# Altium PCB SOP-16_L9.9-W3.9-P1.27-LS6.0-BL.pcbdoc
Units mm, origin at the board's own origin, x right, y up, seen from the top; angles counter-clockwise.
Board outline 23.06 x 20.28 mm, 2 copper layers (Top Layer, Bottom Layer), stack 0 mm thick; 1 components, 0 nets, 16 pads, 0 vias.
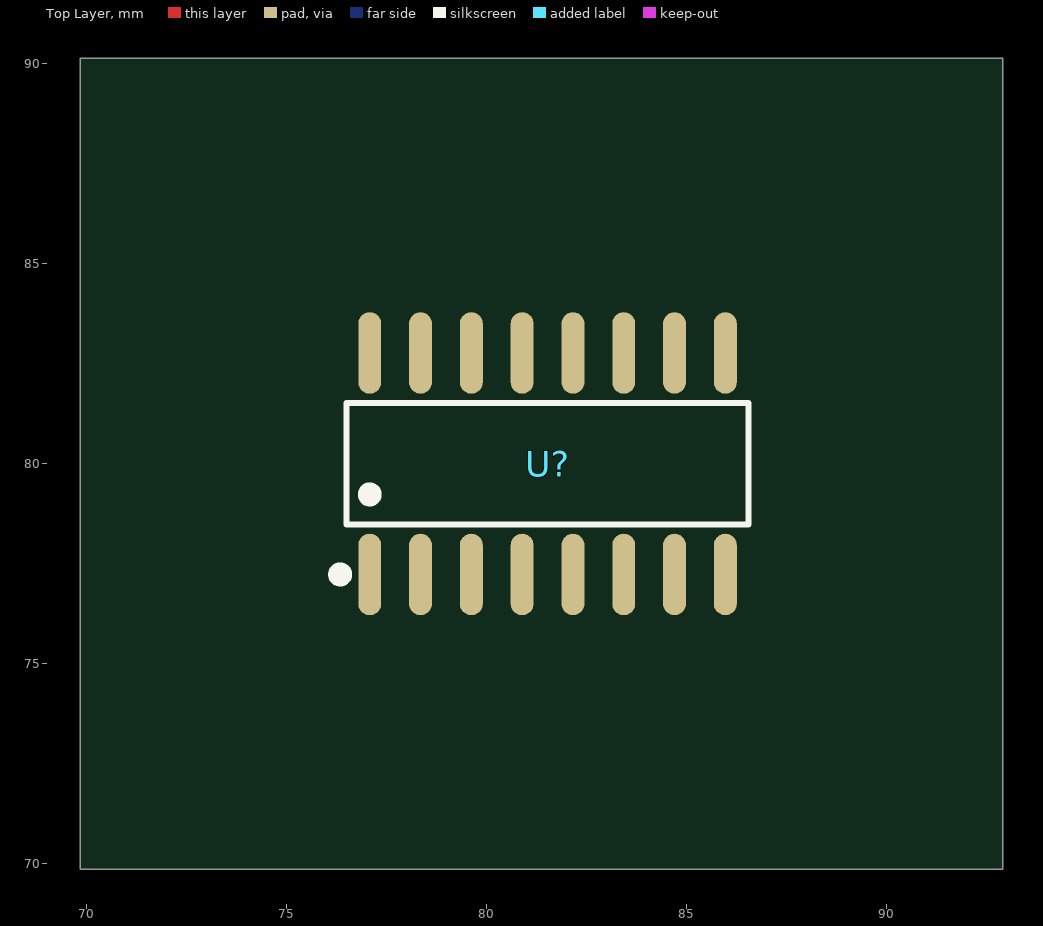
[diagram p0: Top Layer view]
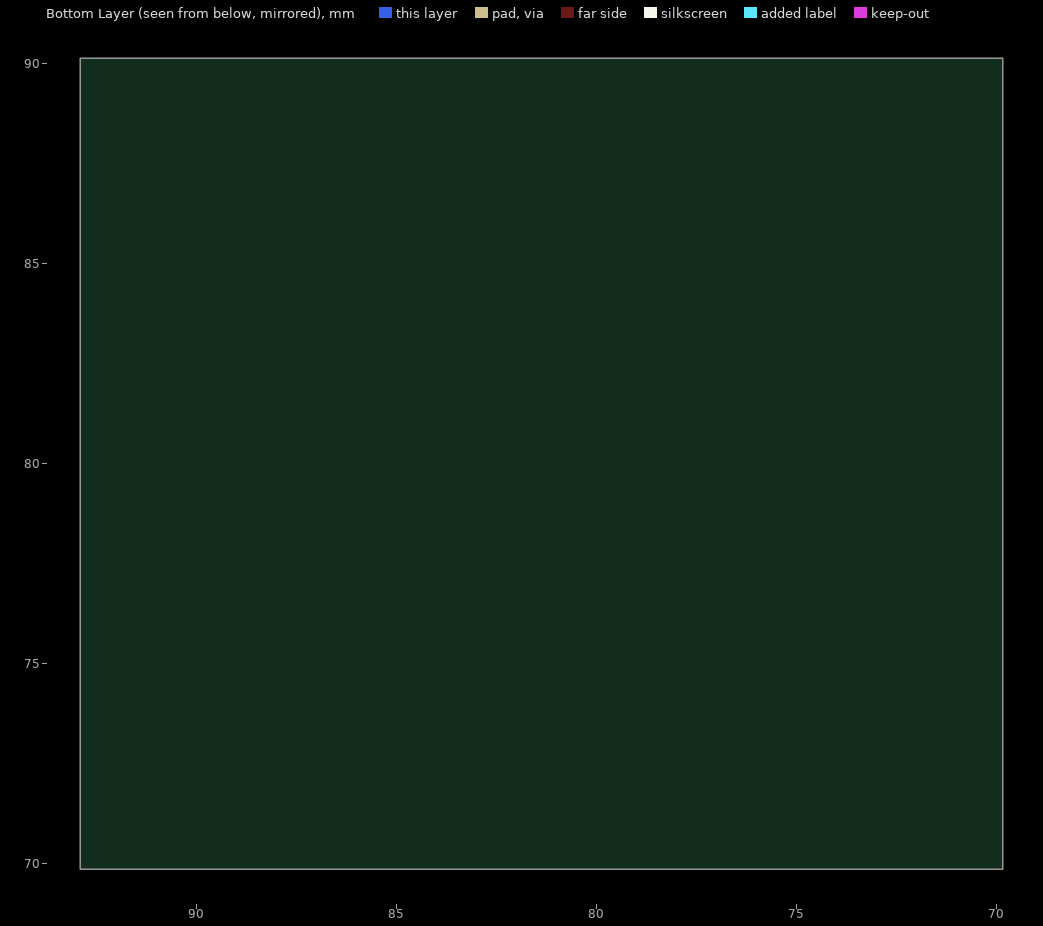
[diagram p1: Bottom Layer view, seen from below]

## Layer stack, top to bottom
Top Layer: signal copper (thickness not stored)
Bottom Layer: signal copper (thickness not stored)

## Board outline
92.911,69.85 69.85,69.85 69.85,90.126 92.911,90.126

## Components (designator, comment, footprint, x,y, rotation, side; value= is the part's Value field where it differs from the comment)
U? "" SOP-16_L9.9-W3.9-P1.27-LS6.0-BL 81.535,79.988 r0 top

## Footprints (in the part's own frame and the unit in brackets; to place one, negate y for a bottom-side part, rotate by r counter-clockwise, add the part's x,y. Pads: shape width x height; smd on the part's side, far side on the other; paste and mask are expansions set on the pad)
SOP-16_L9.9-W3.9-P1.27-LS6.0-BL [mm]
  oval 0.574x2.038 smd: 1(-4.445,-2.769) 2(-3.175,-2.769) 3(-1.905,-2.769) 4(-0.635,-2.769) 5(0.635,-2.769) 6(1.905,-2.769) 7(3.175,-2.769) 8(4.445,-2.769) 9(4.445,2.769) 10(3.175,2.769) 11(1.905,2.769) 12(0.635,2.769) 13(-0.635,2.769) 14(-1.905,2.769) 15(-3.175,2.769) 16(-4.445,2.769)
  silkscreen extent -5.33,-2.92 5.03,1.52

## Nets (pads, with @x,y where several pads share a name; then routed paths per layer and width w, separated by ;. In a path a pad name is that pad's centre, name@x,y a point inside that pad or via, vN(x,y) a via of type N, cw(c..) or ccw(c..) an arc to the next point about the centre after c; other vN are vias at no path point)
pads on no net: U?.1 U?.2 U?.3 U?.4 U?.5 U?.6 U?.7 U?.8 U?.9 U?.10 U?.11 U?.12 U?.13 U?.14 U?.15 U?.16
